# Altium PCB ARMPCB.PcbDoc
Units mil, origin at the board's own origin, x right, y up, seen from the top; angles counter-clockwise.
Board outline 6000 x 4000 mil, 2 copper layers (Top Layer, Bottom Layer); 11 components, 11 nets, 65 pads, 0 vias.
Unrouted connection lines stored in the file: 16.
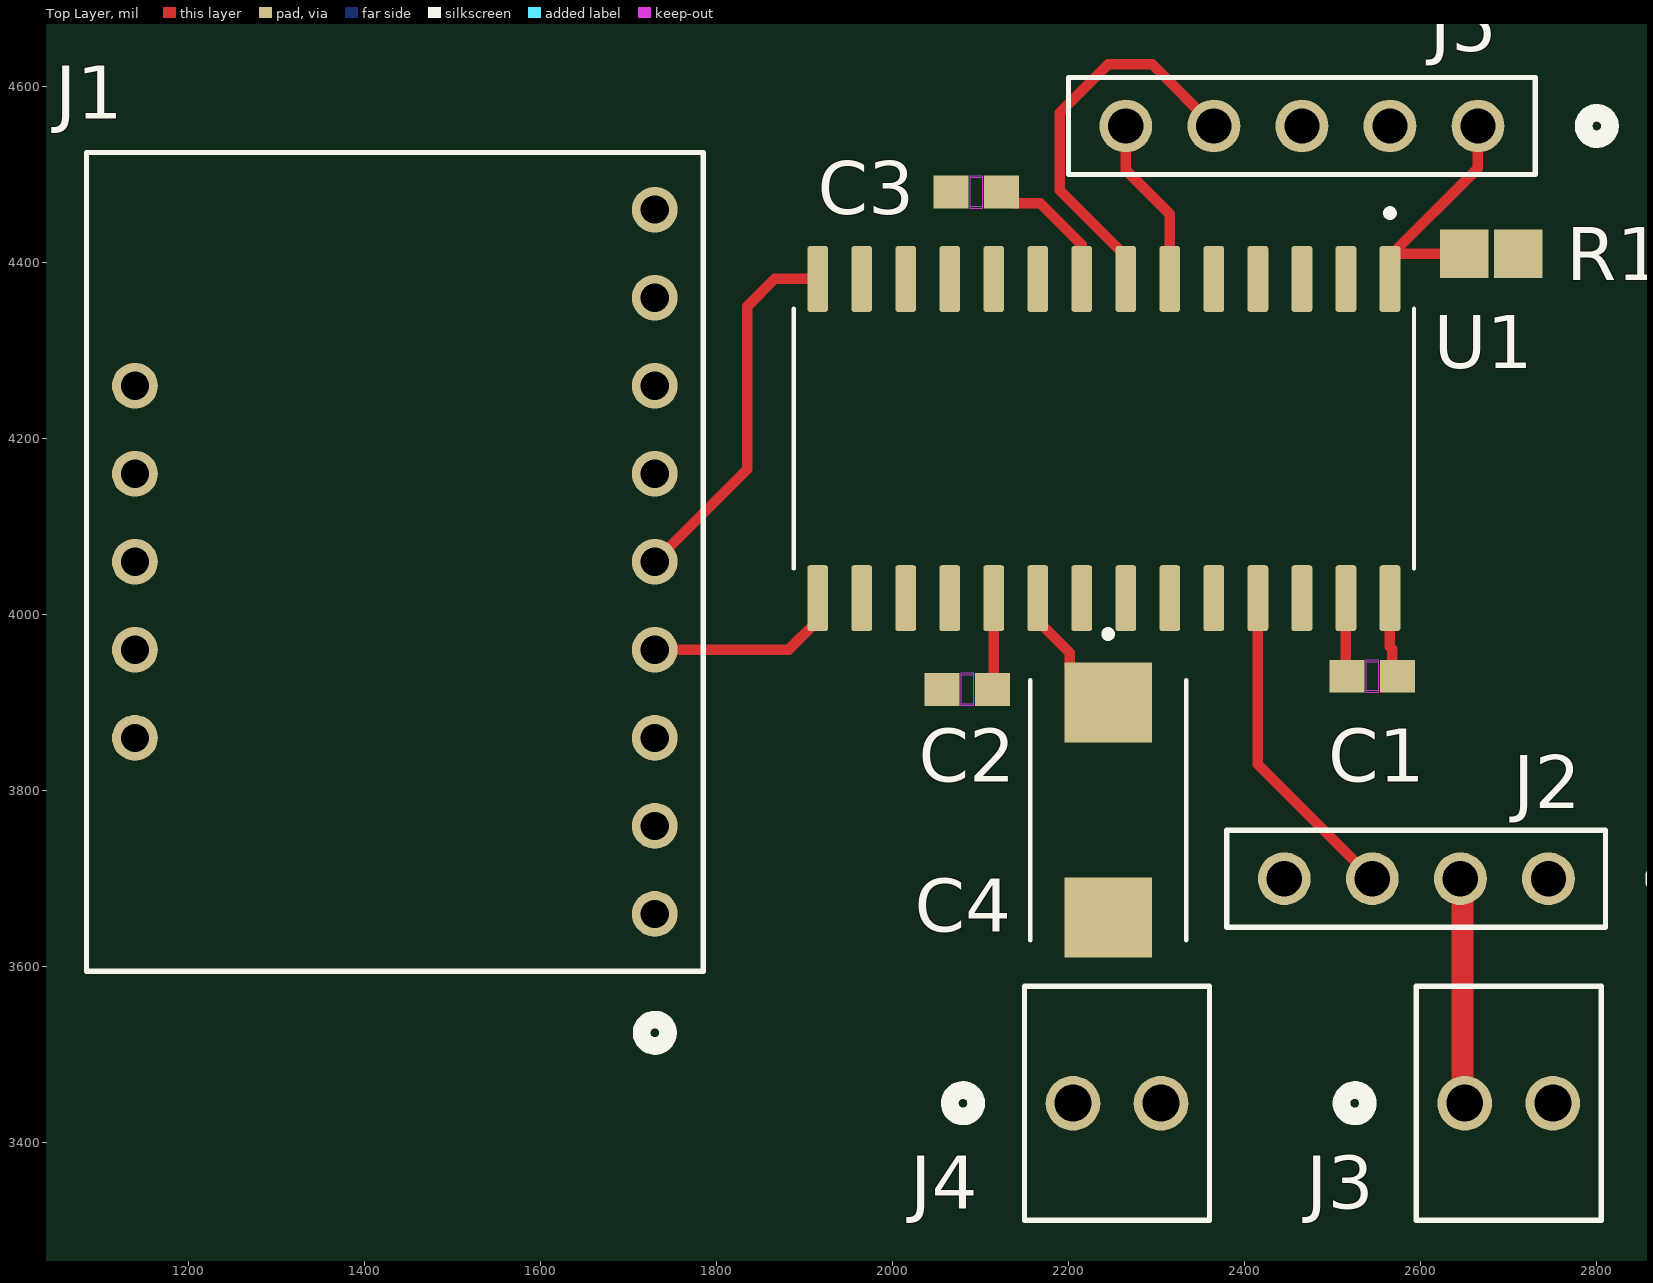
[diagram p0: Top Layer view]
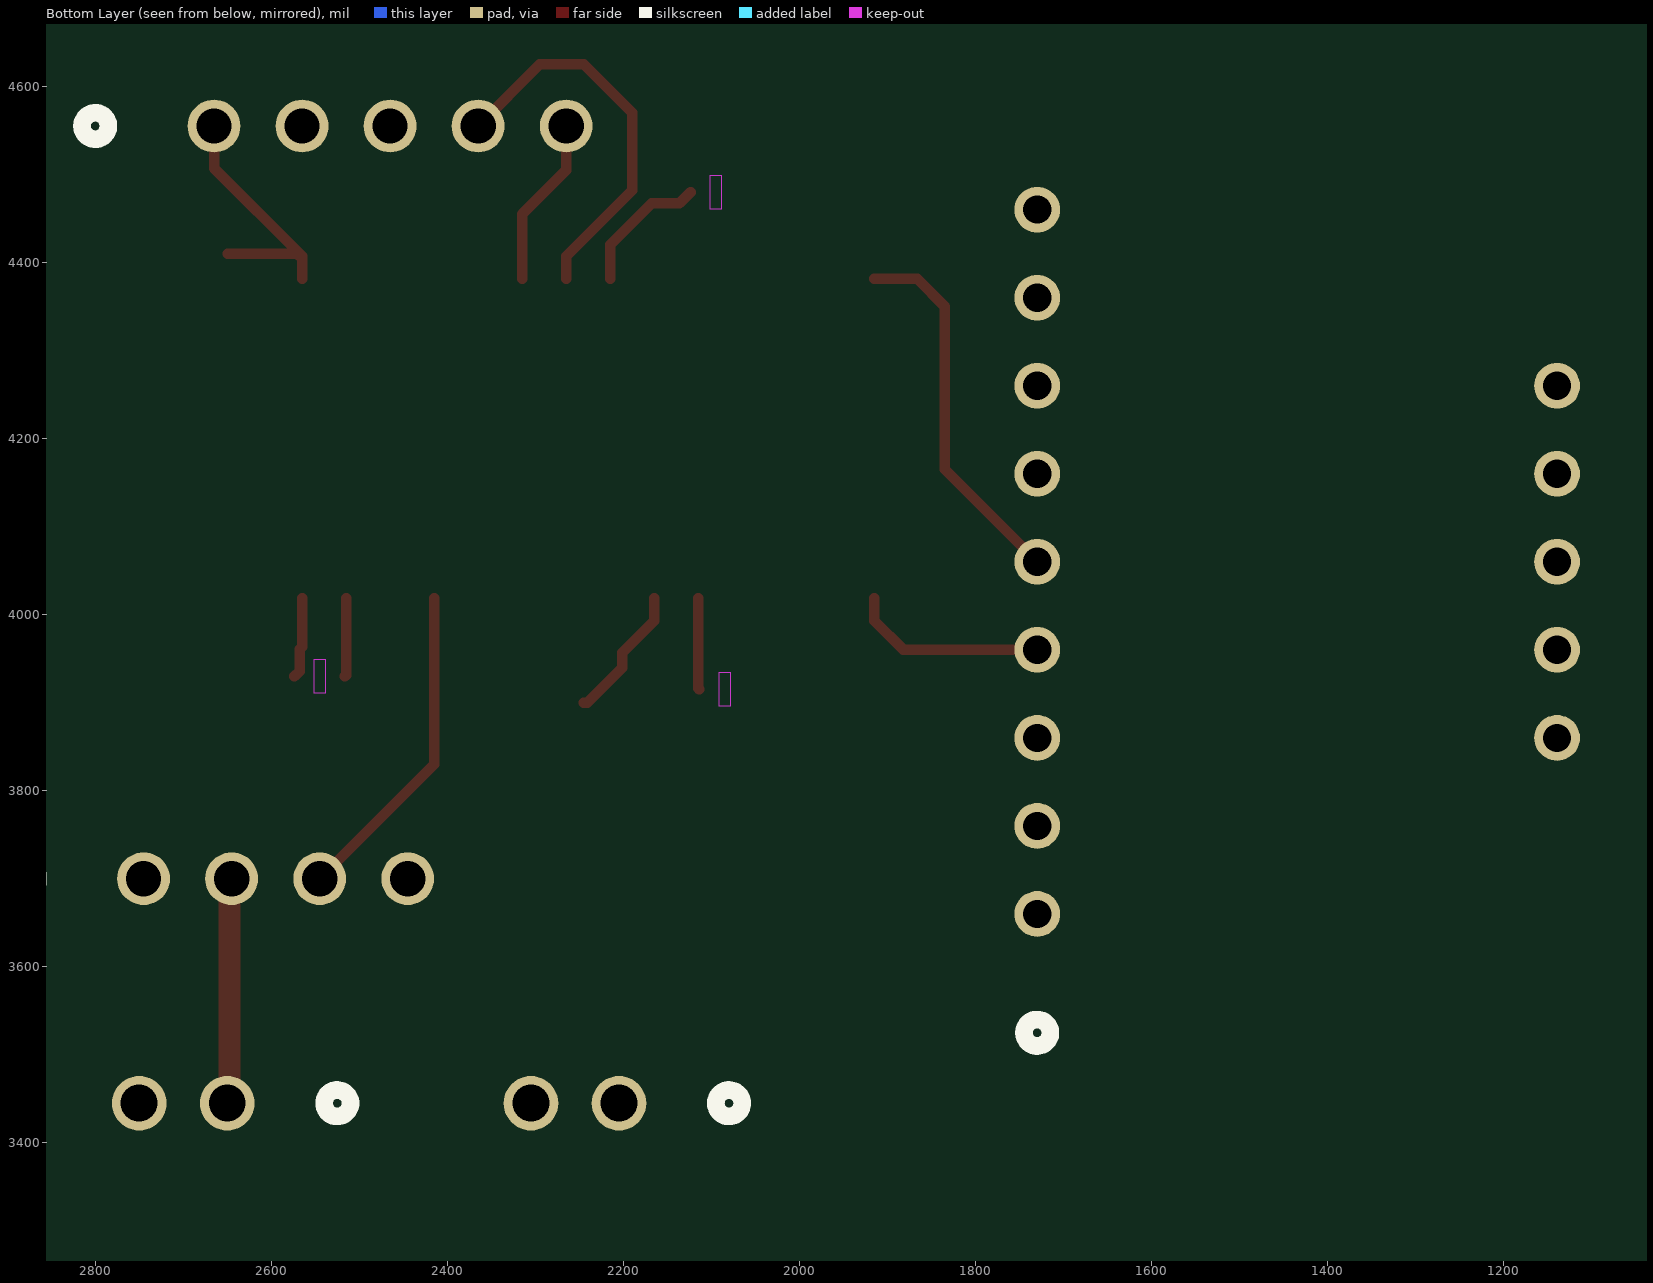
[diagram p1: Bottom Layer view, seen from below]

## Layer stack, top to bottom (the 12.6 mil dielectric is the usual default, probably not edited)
Top Solder: solder mask 0.4, Solder Resist, Dk 3.5
Top Layer: signal copper 1.4
Dielectric 1: dielectric 12.6, FR-4, Dk 4.8
Bottom Layer: signal copper 1.4
Bottom Solder: solder mask 0.4, Solder Resist, Dk 3.5

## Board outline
1000,1000 7000,1000 7000,5000 1000,5000

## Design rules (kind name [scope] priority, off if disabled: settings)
Clearance [All] p1: gap=10 ignorepadtopadclearanceinfootprint=FALSE except(0: Arc-Hole Track-Hole SMDPad-Hole THPad-Hole Via-Hole Fill-Hole Poly-Hole Region-Hole Text-Hole)
PolygonConnect [All] p1: connectstyle=Relief reliefconductorwidth=10 reliefentries=4 polygonreliefangle="90 Angle" airgapwidth=10
RoutingVias [All] p1: holewidth=28 width=50 viastyle="Through Hole" minholewidth=28 minwidth=50 maxholewidth=28 maxwidth=50
SolderMaskExpansion [All] p1: expansion=4 istentingtop=FALSE
Width [All] p1: maxlimit=25 minlimit=6 preferedwidth=12
30 further rules are at their usual default settings.

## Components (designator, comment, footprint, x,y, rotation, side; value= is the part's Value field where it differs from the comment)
C1 "0.10 uF" CAPC17595_95N_KEM 2545,3930 r180 top
C2 "0.10 uF" CAPC17595_95N_KEM 2085,3915 r180 top
C3 "0.10 uF" CAPC17595_95N_KEM 2095,4480 r180 top
C4 "293D106X0035D2TE3" CAPPM7343X310N 2245,3777.95 r270 top
J1 "IMU Connector" "IMU Connector" 1730,3660 r90 top
J2 "ServoMotor" CONN_PPPC041LFBN-RC_SUL 2745,3700 r180 top
J3 "VoltageSource" CONN2_5-3021_MOL 2650,3445 r0 top
J4 "VoltageSource" CONN2_5-3021_MOL 2205,3445 r0 top
J5 "PPPC051LFBN-RC" CONN_PPPC051LFBN-RC_SUL 2665,4555 r180 top
R1 "RNCP0805FTD10K0" RNCP0805FTD10K0_V2 2680,4410 r0 top value="10 kOhms ±1%"
U1 "DSPIC33EV32GM002-I/SO" SOIC127P1030X265-28N 2240,4200 r270 top

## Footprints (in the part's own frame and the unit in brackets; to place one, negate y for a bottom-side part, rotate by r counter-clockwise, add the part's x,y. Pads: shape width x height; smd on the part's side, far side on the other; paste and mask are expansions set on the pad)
CAPC17595_95N_KEM [mm]
  rect 1.006x0.95 smd paste+0 mask+0: 1(-0.728,0) 2(0.728,0)
  Top Layer keep-out region: -0.174,-0.424 -0.174,0.424 0.174,0.424 0.174,-0.424
  Keep-Out Layer region: -0.174,-0.475 -0.174,0.475 0.174,0.475 0.174,-0.475
  body extent -0.87,-0.48 0.87,0.48, height 0.95
CAPPM7343X310N [mm]
  rect 2.31x2.52 smd: 1(-3.1,0) 2(3.1,0)
  silkscreen extent -5.18,-2.25 3.75,2.25
CONN2_5-3021_MOL [mil]
  round 62 / inner round 60 / far side round 62 hole 42 paste-99999 mask+0: 1(0,0) 2(100,0)
  silkscreen extent -140,-133 155,133
CONN_PPPC041LFBN-RC_SUL [mil]
  round 60 hole 40 paste-99999 mask-30: 1(0,0) 2(100,0) 3(200,0) 4(300,0)
  silkscreen extent -150,-55 365,55
CONN_PPPC051LFBN-RC_SUL [mil]
  round 60 hole 40 paste-99999 mask-30: 1(0,0) 2(100,0) 3(200,0) 4(300,0) 5(400,0)
  silkscreen extent -150,-55 465,55
"IMU Connector" [mil]
  round 52 / inner round 60 / far side round 52 hole 32 paste-99999 mask+0: 1(0,0) 2(100,0) 3(200,0) 4(300,0) 5(400,0) 6(500,0) 7(600,0) 8(700,0) 9(800,0) 10(200,590.55) 11(300,590.55) 12(400,590.55) 13(500,590.55) 14(600,590.55)
  silkscreen extent -150,-55 865,646
RNCP0805FTD10K0_V2 [mm] "Chip Resistor, 2-Leads, Body 2.00x1.25mm, IPC Medium Density"
  rect 1.4x1.4 smd: 1(-0.775,0) 2(0.775,0)
  body extent -1.07,-0.7 1.07,0.7, height 0.65
SOIC127P1030X265-28N [mm]
  rrect25% 1.9x0.6 smd: 1(-4.605,8.255) 2(-4.605,6.985) 3(-4.605,5.715) 4(-4.605,4.445) 5(-4.605,3.175) 6(-4.605,1.905) 7(-4.605,0.635) 8(-4.605,-0.635) 9(-4.605,-1.905) 10(-4.605,-3.175) 11(-4.605,-4.445) 12(-4.605,-5.715) 13(-4.605,-6.985) 14(-4.605,-8.255) 15(4.605,-8.255) 16(4.605,-6.985) 17(4.605,-5.715) 18(4.605,-4.445) 19(4.605,-3.175) 20(4.605,-1.905) 21(4.605,-0.635) 22(4.605,0.635) 23(4.605,1.905) 24(4.605,3.175) 25(4.605,4.445) 26(4.605,5.715) 27(4.605,6.985) 28(4.605,8.255)
  silkscreen extent -6.6,-8.95 3.75,8.95, body extent -5.15,-8.95 5.15,8.95, height 2.65

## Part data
C1 C2 C3: library part CerCap, "CAP CER 0.1UF", Capacitance="0.10 μF", Manufacturer=KEMET, Manufacturer Part Number=C0603C104K5RACTU, Package=C0603C-CF, Temperature="-55°C to +125°C", Temperature Characteristic=X7R, Temperature Coefficient=30ppm/°C, Temperature Range High=+125°C, Temperature Range Low=-55°C, Tolerance=0.1, Voltage Rating="50 V"
C4: "Capacitor: tantalum; 10uF; 35VDC; SMD; Case: D; Â±20%; -55Ã·125Â°C", Package=None
J1: "LSM9DS1 ACCEL/MAG/GYRO/TEMP BRD Connections"
J2: Supplier Part Number 1=900-00360-ND
J5: "Female, 5 C, Straight, .100\"CC; 3.20mm Tail, No Mounting; PBT, Phos. Bronze, 105 C", Color=Black, Manufacturer=Sullins, Package Quantity=1000, Supplier Part Number 1=8009019
R1: library part CMP-005-000019-1, "RES 10K OHM 1% 1/4W 0805"
U1: Supplier Part Number 1=DSPIC33EV32GM002-I/SO-ND

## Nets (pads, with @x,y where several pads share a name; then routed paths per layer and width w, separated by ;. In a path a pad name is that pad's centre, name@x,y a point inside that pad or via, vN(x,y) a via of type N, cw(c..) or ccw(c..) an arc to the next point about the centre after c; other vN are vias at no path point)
5V: C1.1 C2.2 C3.2 J1.1 J4.1 J5.2 R1.2 U1.13 U1.28 | length 92.3
  Top Layer w12: U1.28 2565,3963.3 2567.86,3960.44 2567.86,3935.8 C1.1
6V: J2.2 J3.1 | length 257.1
  Top Layer w25: J2.2 2647.5,3697.5 2647.5,3447.5 J3.1
GND: C1.2 C2.1 C3.1 C4.2 J1.3 J2.1 J3.2 J4.2 J5.3 U1.8 U1.19 U1.27 | length 348.4
  Top Layer w12: C2.1 2115,3916.35 U1.19 ; C3.1 2136.35,4467.3 2167.7,4467.3 2215,4420 U1.8 ; U1.27 2515,3931.35 C1.2
MCLR: J5.1 R1.1 U1.1 | length 302
  Top Layer w12: U1.1 U1.1@2565,4404.19 ; R1.1 2570.81,4410 U1.1@2565,4404.19 ; J5.1 2665,4506.89 2565,4406.89 U1.1@2565,4404.19
MotorCtrlH: J2.3 U1.25 | length 372.5
  Top Layer w12: U1.25 2415,3830 J2.3
MotorFdbk: J2.4 U1.17
NetC4_1: C4.1 U1.20 | length 154.3
  Top Layer w12: U1.20 2165,3993.11 2201.39,3956.72 2201.39,3939.47 2240.87,3900 C4.1
PGEC: J5.5 U1.6 | length 194.4
  Top Layer w12: J5.5 2265,4505 2315,4455 U1.6
PGED: J5.4 U1.7 | length 446.5
  Top Layer w12: U1.7 2265,4406.89 2190,4481.89 2190,4570 2245,4625 2295,4625 J5.4
SCL: J1.4 U1.15 | length 224.3
  Top Layer w12: J1.4 1881.89,3960 1915,3993.11 U1.15
SDA: J1.5 U1.14 | length 426.5
  Top Layer w12: J1.5 1835,4165 1835,4350 1866.3,4381.3 U1.14
pads on no net: J1.2 J1.6 J1.7 J1.8 J1.9 J1.10 J1.11 J1.12 J1.13 J1.14 U1.2 U1.3 U1.4 U1.5 U1.9 U1.10 U1.11 U1.12 U1.16 U1.18 U1.21 U1.22 U1.23 U1.24 U1.26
